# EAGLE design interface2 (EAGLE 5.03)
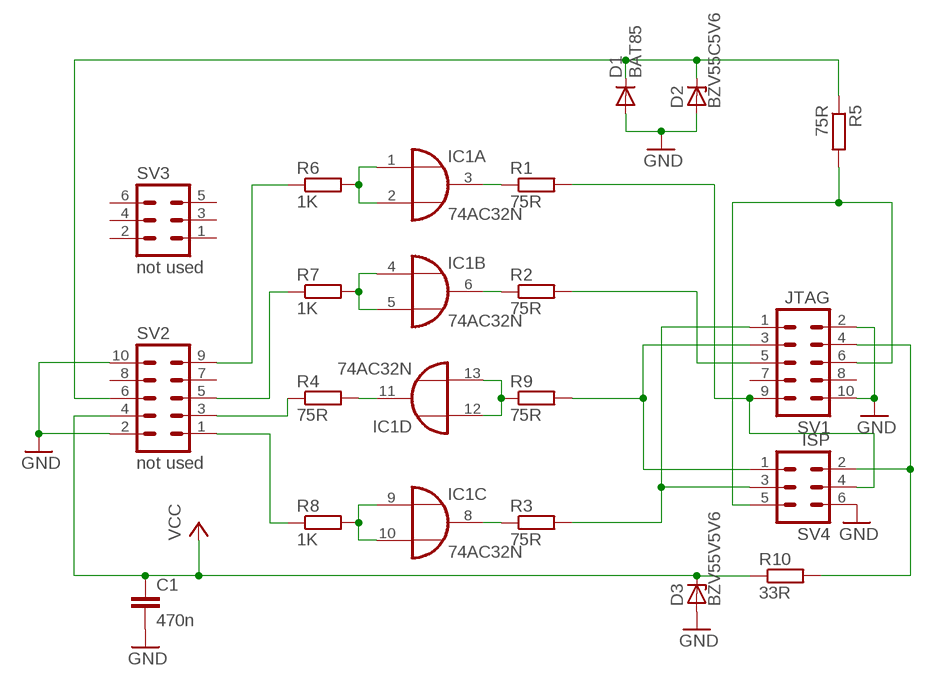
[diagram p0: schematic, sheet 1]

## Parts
C1  470n  C2.5P  [C025-030X050]
D1  BAT85  1N4148  [DO34-7]
D2  BZV55C5V6  ZENERDIODE  [DO34Z7]
D3  BZV55V5V6  ZENERDIODE  [DO34Z7]
IC1  74AC32N  [DIL14]
R1  75R  R  [0207/10]
R2  75R  R  [0207/10]
R3  75R  R  [0207/10]
R4  75R  R  [0207/10]
R5  75R  R  [0207/10]
R6  1K  R  [0207/10]
R7  1K  R  [0207/10]
R8  1K  R  [0207/10]
R9  75R  R  [0207/10]
R10  33R  R  [0207/10]
SV1  JTAG  ML10L  [ML10L]
SV2  not used  MA05-2  [MA05-2]
SV3  not used  MA03-2  [MA03-2]
SV4  ISP  ML6L  [ML6L]

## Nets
GND [supply]: C1.2 D1.A D2.A D3.A SV1.2 SV1.10 SV2.2 SV2.10 SV4.6
N$1: IC1.3(A:O) R1.1
N$2: IC1.6(B:O) R2.1
N$3: IC1.8(C:O) R3.1
N$4: IC1.11(D:O) R4.2
N$5: IC1.4(B:I0) IC1.5(B:I1) R7.2
N$6: IC1.12(D:I0) IC1.13(D:I1) R9.1
N$7: IC1.9(C:I0) IC1.10(C:I1) R8.2
N$8: IC1.1(A:I0) IC1.2(A:I1) R6.2
N$9: R5.2 SV1.6 SV4.5
N$10: D1.C D2.C R5.1 SV2.6
N$11: R9.2 SV1.3 SV4.1
N$12: R1.2 SV1.9 SV4.4
N$13: R2.2 SV1.5
N$14: R3.2 SV1.1 SV4.3
N$17: R6.1 SV2.9
N$18: R7.1 SV2.5
N$19: R4.1 SV2.3
N$20: R8.1 SV2.1
N$21: R10.2 SV1.4 SV4.2
VCC [supply]: C1.1 D3.C R10.1 SV2.4
Unconnected: SV1.7 SV1.8 SV2.7 SV2.8 SV3.1 SV3.2 SV3.3 SV3.4 SV3.5 SV3.6

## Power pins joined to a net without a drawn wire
GND: IC1.7(P:GND)
VCC: IC1.14(P:VCC)

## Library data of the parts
C1 = ee2parts:C: Capacitor
D1 = ee2parts:1N4148: DIODE
D2 D3 = ee2parts:ZENERDIODE: Z DIODE
IC1 = 74xx-eu:74*32: Quad 2-input OR gate
R1-R10 = ee2parts:R: Resistor
SV1 = con-ml:ML10L: HARTING
SV2 = con-lstb:MA05-2: PIN HEADER
SV3 = con-lstb:MA03-2: PIN HEADER
SV4 = con-ml:ML6L: HARTING

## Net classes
1 supply: width 1.27 mm

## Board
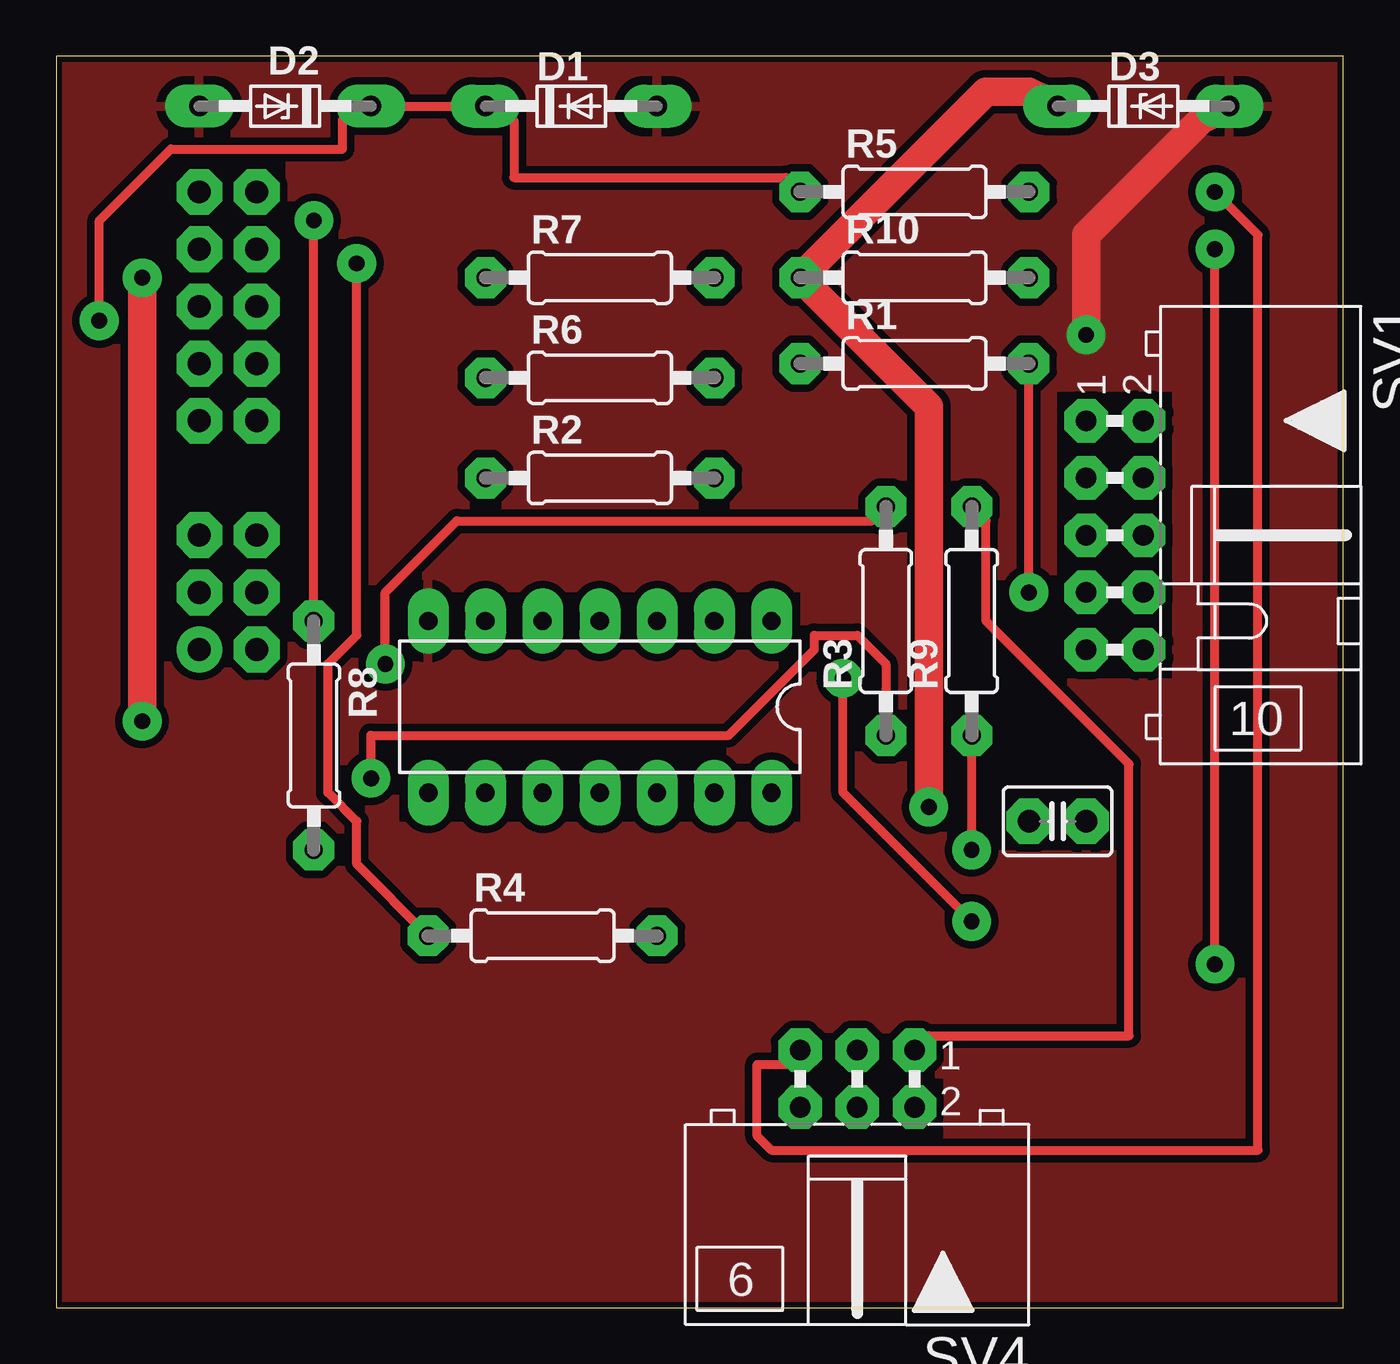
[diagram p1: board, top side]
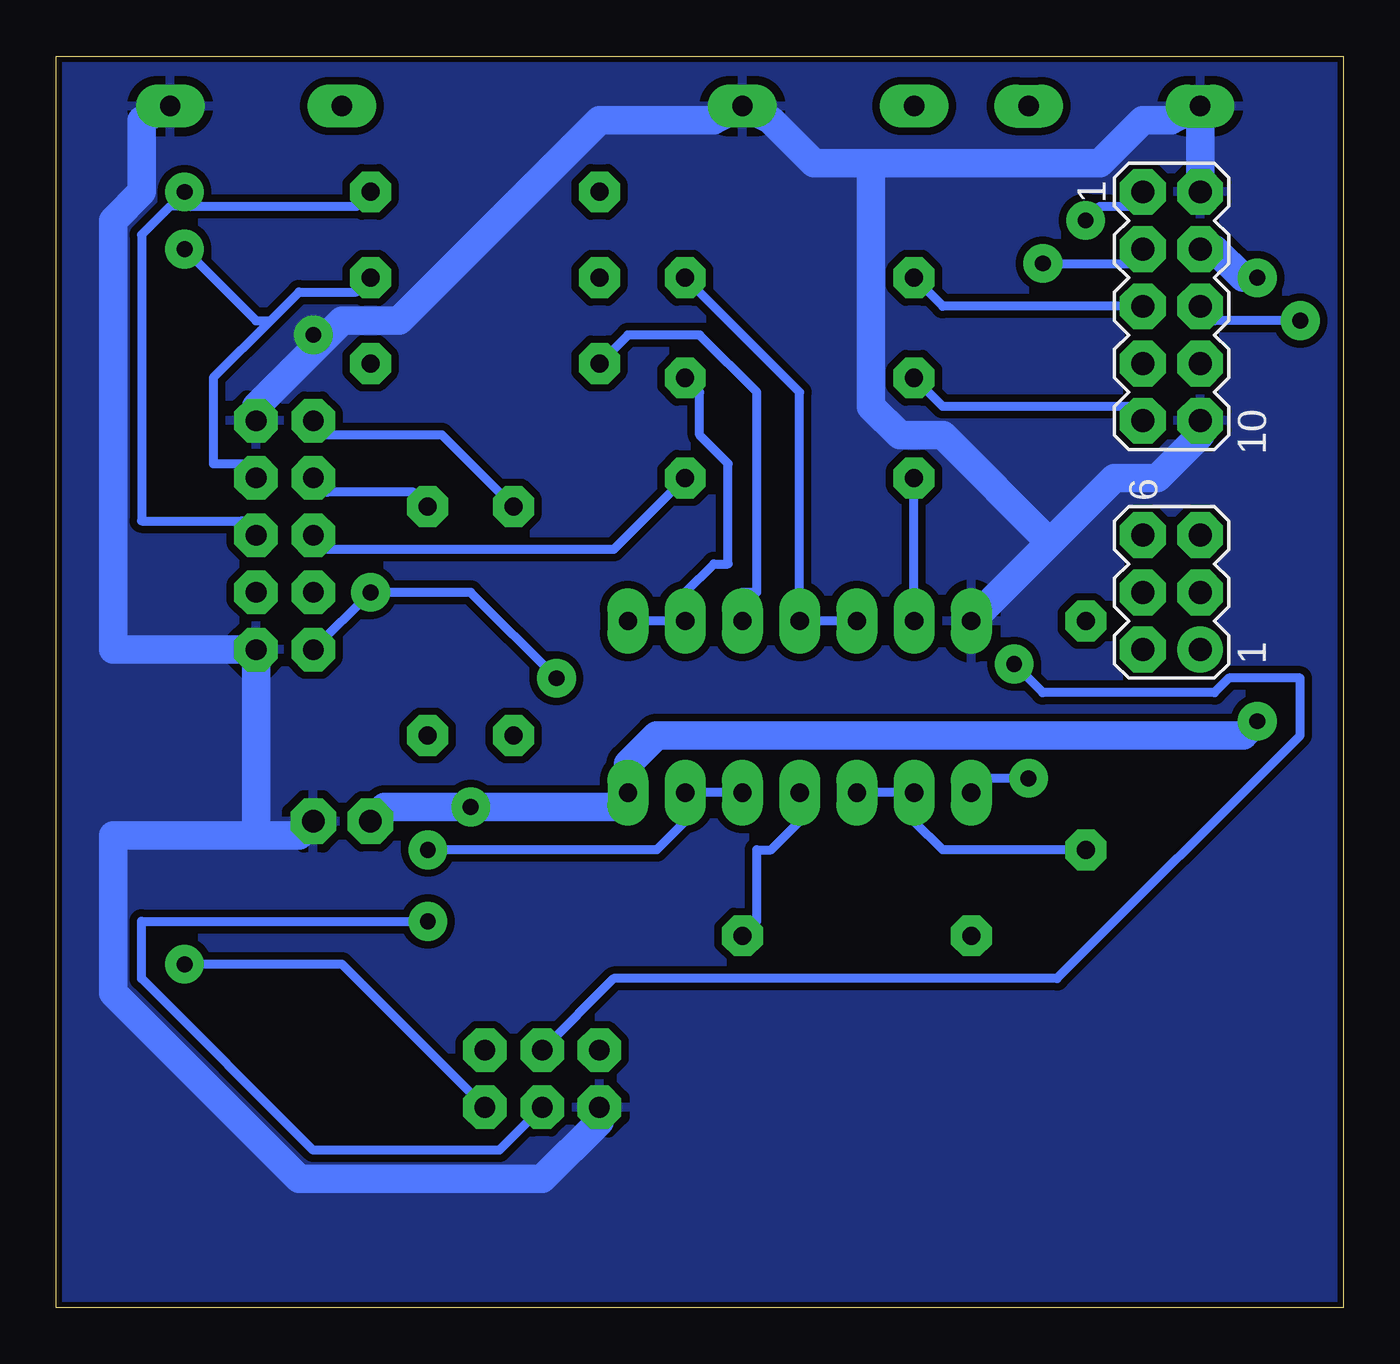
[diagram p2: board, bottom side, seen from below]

Size 57.13 x 55.55 mm. Coordinates in mm from the lower left corner, seen from the top.
Outline: 0,0 57.13,0 57.13,55.55 0,55.55 0,0
Copper layers (1*16): Top 0.035mm / dielectric 1.5mm / Bottom 0.035mm
Design rules "zigbit_rules": minimum track width 16mil, minimum drill 0.7mm, track to track 13mil, track to pad 13mil, pad to pad 13mil, via to via 13mil, smd to smd 0mil, copper to edge 10mil, drill to drill 10mil, minimum pad ring 20mil, minimum via ring 20mil, stop-mask expansion 0mil, vias tented up to drill 0mil, thermal gap 15mil
tRestrict: area 44.5,27.9 to 49.5,40.6; area 5.1,38.1 to 10.2,50.8; area 31.7,7.6 to 39.4,10.2; area 41.9,20.3 to 47,22.9; area 15.2,29.2 to 33,31.8; area 15.2,21.6 to 33,24.1
vRestrict: area 48.3,22.9 to 58.4,45.7; area 26.7,0 to 44.5,8.9

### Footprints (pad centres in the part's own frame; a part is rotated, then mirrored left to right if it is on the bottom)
C025-030X050 = drill 1 octagon: 1 -1.27,0; 2 1.27,0
DO34-7 = drill 0.9 long: A 3.81,0; C -3.81,0
DO34Z7 = drill 0.9 long: A 3.81,0; C -3.81,0
DIL14 = drill 0.813 long: 1 -7.62,-3.81; 2 -5.08,-3.81; 3 -2.54,-3.81; 4 0,-3.81; 5 2.54,-3.81; 6 5.08,-3.81; 7 7.62,-3.81; 8 7.62,3.81; 9 5.08,3.81; 10 2.54,3.81; 11 0,3.81; 12 -2.54,3.81; 13 -5.08,3.81; 14 -7.62,3.81
0207/10 = drill 0.8 octagon: 1 -5.08,0; 2 5.08,0
ML10L = drill 0.914 octagon: 1 -5.08,-1.27; 2 -5.08,1.27; 3 -2.54,-1.27; 4 -2.54,1.27; 5 0,-1.27; 6 0,1.27; 7 2.54,-1.27; 8 2.54,1.27; 9 5.08,-1.27; 10 5.08,1.27
MA05-2 = drill 1.016 octagon: 1 -5.08,-1.27; 2 -5.08,1.27; 3 -2.54,-1.27; 4 -2.54,1.27; 5 0,-1.27; 6 0,1.27; 7 2.54,-1.27; 8 2.54,1.27; 9 5.08,-1.27; 10 5.08,1.27
MA03-2 = drill 1.016 round: 1 -2.54,-1.27 | drill 1.016 octagon: 2 -2.54,1.27; 3 0,-1.27; 4 0,1.27; 5 2.54,-1.27; 6 2.54,1.27
ML6L = drill 0.914 octagon: 1 -2.54,-1.27; 2 -2.54,1.27; 3 0,-1.27; 4 0,1.27; 5 2.54,-1.27; 6 2.54,1.27

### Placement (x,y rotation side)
C1  44.45,21.59 0 top
D1  22.86,53.34 0 top
D2  10.16,53.34 180 top
D3  48.26,53.34 0 top
IC1  24.13,26.67 180 top
R1  38.1,41.91 0 top
R2  24.13,36.83 0 top
R3  36.83,30.48 90 top
R4  21.59,16.51 0 top
R5  38.1,49.53 0 top
R6  24.13,41.27 0 top
R7  24.13,45.72 0 top
R8  11.43,25.4 270 top
R9  40.64,30.48 90 top
R10  38.1,45.72 0 top
SV1  46.99,34.29 270 top
SV2  7.62,44.45 270 bottom
SV3  7.62,31.75 90 bottom
SV4  35.56,10.16 180 top

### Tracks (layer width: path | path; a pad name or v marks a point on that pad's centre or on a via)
GND  (via drill 0.7)
  Top 1.27: v45.72,43.18 45.72,47.62 50.8,52.7 D3.A
  Bottom 1.27: D3.A 53.34,52.7 53.34,49.53 54.61,48.26 54.61,29.21 SV1.10 48.26,20.96 | 48.26,20.96 46.35,20.96 C1.2 | 48.26,20.96 54.61,20.96 54.61,13.97 46.35,5.71 35.56,5.71 33.02,8.26 SV4.6 | 13.02,33.97 10.16,36.83 8.25,36.83 6.35,38.73 SV2.10 | 13.02,33.97 IC1.7 | SV2.2 D2.A 7.62,52.7 8.89,52.7 10.8,50.8 20.95,50.8 | 20.95,50.8 23.49,50.8 25.4,52.7 D1.A 27.94,52.7 33.02,52.7 41.91,43.81 44.45,43.81 45.4,42.86 | 45.4,42.86 48.26,40 SV1.2 | 20.95,50.8 20.95,40 19.68,38.73 17.78,38.73 13.02,33.97 | v45.72,43.18 45.4,42.86
  pour Top: 0,55.88 57.15,55.88 57.15,0 0,0
  pour Bottom: 0,55.88 57.15,55.88 57.15,0 0,0
N$1
  Bottom 0.406: R1.1 31.75,43.18 28.58,43.18 26.04,40.64 26.04,31.75 26.67,31.75 IC1.3
N$2
  Bottom 0.406: IC1.6 R2.1
N$3  (via drill 0.7)
  Top 0.406: v13.97,23.5 13.97,25.4 29.84,25.4 33.66,29.21 33.66,29.84 35.56,29.84 36.83,28.58 R3.1
  Bottom 0.406: v13.97,23.5 15.88,23.5 IC1.8
N$4
  Bottom 0.406: R4.2 26.04,17.14 26.04,20.32 25.4,20.32 24.13,21.59 IC1.11
N$5
  Bottom 0.406: R7.2 24.13,40.64 IC1.4 IC1.5
N$6  (via drill 0.7)
  Top 0.406: v40.64,20.32 R9.1
  Bottom 0.406: v40.64,20.32 30.48,20.32 29.21,21.59 IC1.13 IC1.12
N$7
  Bottom 0.406: R8.2 17.78,20.32 19.05,21.59 IC1.9 IC1.10
N$8
  Bottom 0.406: R6.2 28.58,40.64 28.58,38.73 27.3,37.47 27.3,33.02 27.94,33.02 29.21,31.75 IC1.2 IC1.1
N$9  (via drill 0.7)
  Top 0.406: v51.44,49.53 53.34,47.62 53.34,6.98 31.75,6.98 31.12,7.62 31.12,10.79 32.38,10.79 SV4.5
  Bottom 0.406: 51.44,48.89 52.07,48.89 53.34,47.62 53.34,34.92 48.9,34.92 SV1.6 | 51.44,48.89 43.81,48.89 R5.2 | v51.44,49.53 51.44,48.89
N$10  (via drill 0.7)
  Top 0.406: R5.1 32.38,50.16 20.32,50.16 20.32,52.7 D1.C D2.C 12.7,52.7 12.7,51.44 5.08,51.44 1.91,48.26 v1.91,43.81
  Bottom 0.406: v1.91,43.81 5.71,43.81 SV2.6
N$11
  Top 0.406: SV4.1 38.73,12.06 47.62,12.06 47.62,24.13 41.27,30.48 41.27,34.92 R9.2
  Bottom 0.406: R9.2 41.27,36.2 45.09,36.2 SV1.3
N$12  (via drill 0.7)
  Top 0.406: v43.18,31.75 R1.2 | v40.64,17.14 34.92,22.86 v34.92,27.94
  Bottom 0.406: SV1.9 v43.18,31.75 38.73,31.75 v34.92,27.94 | v40.64,17.14 53.34,17.14 53.34,14.61 45.72,6.98 37.47,6.98 SV4.4
N$13
  Bottom 0.406: R2.2 32.38,33.66 45.09,33.66 SV1.5
N$14  (via drill 0.7)
  Top 0.406: v14.61,28.58 14.61,31.75 17.78,34.92 36.2,34.92 R3.2
  Bottom 0.406: R3.2 40.01,38.73 45.09,38.73 SV1.1 | v14.61,28.58 13.34,27.3 5.71,27.3 5.08,27.94 1.91,27.94 1.91,25.4 12.7,14.61 32.38,14.61 SV4.3
N$17
  Bottom 0.406: R6.1 17.78,40 9.52,40 SV2.9
N$18
  Bottom 0.406: R7.1 17.78,44.45 SV2.5
N$19  (via drill 0.7)
  Top 0.406: v13.34,46.36 13.34,29.84 12.07,28.58 12.07,22.86 13.34,21.59 13.34,19.68 R4.1
  Bottom 0.406: v13.34,46.36 9.52,46.36 SV2.3
N$20  (via drill 0.7)
  Top 0.406: R8.1 v11.43,48.26
  Bottom 0.406: v11.43,48.26 10.8,48.89 9.52,48.89 SV2.1
N$21  (via drill 0.7)
  Top 0.406: v51.44,15.24 v51.44,46.99
  Bottom 0.406: 47.62,43.81 50.16,41.27 50.16,37.47 48.9,37.47 SV1.4 | 47.62,43.81 46.35,45.09 43.81,45.09 R10.2 | v51.44,15.24 44.45,15.24 SV4.2 | v51.44,46.99 48.26,43.81 47.62,43.81
VCC  (via drill 0.7)
  Top 1.27: D3.C 43.18,53.98 41.27,53.98 R10.1 38.73,40 v38.73,22.23 | v3.81,26.04 v3.81,45.72
  Bottom 1.27: C1.1 42.55,22.23 v38.73,22.23 32.38,22.23 IC1.14 31.75,24.13 30.48,25.4 4.45,25.4 v3.81,26.04 | v3.81,45.72 4.45,45.72 5.71,46.99 SV2.4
